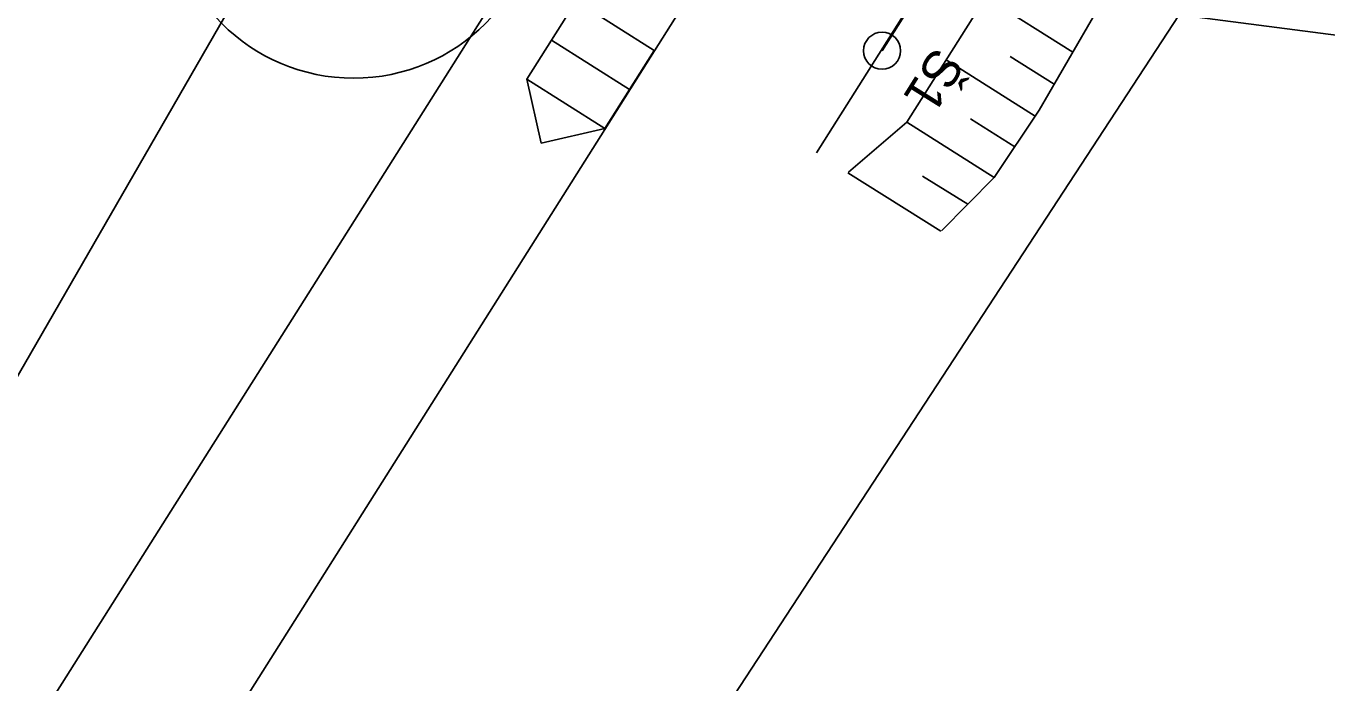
# Model space of a CAD drawing. Extents: x -746176 to -739709, y -1128407 to -1124482.
# Drawn here: x -743187.21 to -743169.62, y -1127113.64 to -1127104.75 of the extents above; entities that cross this region are included whole.
import ezdxf

# ---------------------------------------------------------------- set-up
doc = ezdxf.new("R2010")
doc.units = 0
for name, color, linetype in [('_Zabezpečovací zařízení', 7, 'Continuous'), ('_Zabezpečovací zařízení_trasa', 7, 'Continuous'), ('Hranice parcel', 7, 'Continuous'), ('OSA', 7, 'Continuous'), ('SMER_VYS_VYROVNANI', 7, 'Continuous'), ('SVAH', 7, 'Continuous'), ('TRATIVOD', 7, 'Continuous'), ('Vrstva 53', 7, 'Continuous'), ('ŽBP', 7, 'Continuous')]:
    doc.layers.add(name, color=color, linetype=linetype)

msp = doc.modelspace()

# ---------------------------------------------------------------- linework, layer by layer
at = {"layer": '_Zabezpečovací zařízení'}
for p, q in [((-743179.773, -1127104.416), (-743180.44, -1127105.473)), ((-743178.716, -1127105.083), (-743179.773, -1127104.416)), ((-743179.05, -1127105.611), (-743180.107, -1127104.945)), ((-743179.383, -1127106.14), (-743178.716, -1127105.083)), ((-743180.44, -1127105.473), (-743179.383, -1127106.14)), ((-743180.44, -1127105.473), (-743180.245, -1127106.335)), ((-743180.245, -1127106.335), (-743179.383, -1127106.14))]:
    msp.add_line(p, q, dxfattribs=at)
msp.add_lwpolyline([(-743179.773, -1127104.416), (-743180.107, -1127104.945), (-743179.05, -1127105.611), (-743178.716, -1127105.083), (-743179.773, -1127104.416)], dxfattribs=at)
at = {"layer": '_Zabezpečovací zařízení_trasa'}
msp.add_lwpolyline([(-743018.819, -1126847.736), (-743049.28, -1126895.951), (-743072.487, -1126932.751), (-743098.647, -1126974.146), (-743125.94, -1127017.384), (-743152.604, -1127059.608), (-743175.023, -1127095.116), (-743199.163, -1127133.346), (-743215.971, -1127159.941), (-743232.818, -1127186.515), (-743247.456, -1127209.811), (-743254.52, -1127221.639), (-743261.299, -1127233.691), (-743264.155, -1127239.195), (-743264.862, -1127241.108), (-743267.337, -1127245.816), (-743268.289, -1127247.159), (-743271.711, -1127253.75), (-743281.122, -1127274.196), (-743291.923, -1127301.42), (-743296.724, -1127315.222), (-743301.116, -1127329.128), (-743306.787, -1127349.506)], dxfattribs=at)
at = {"layer": 'Hranice parcel'}
for q in [(-743183.01, -1127122.02), (-743100.85, -1127113.88)]:
    msp.add_line((-743171.62, -1127104.6), q, dxfattribs=at)
msp.add_lwpolyline([(-743280.26, -1127263.68), (-743264.54, -1127233.06), (-743246.95, -1127204.21), (-743235.54, -1127186.77), (-743205.03, -1127140.21), (-743183.34, -1127102.57)], dxfattribs=at)
at = {"layer": 'OSA'}
msp.add_lwpolyline([(-743169.53, -1127090.542), (-743178.712, -1127105.086)], dxfattribs=at)
at = {"layer": 'SMER_VYS_VYROVNANI'}
msp.add_lwpolyline([(-743178.712, -1127105.086), (-743197.526, -1127134.888)], dxfattribs=at)
at = {"layer": 'SVAH'}
for p, q in [((-743173.059, -1127105.107), (-743174.235, -1127104.364)), ((-743173.565, -1127105.97), (-743174.769, -1127105.21)), ((-743173.309, -1127105.54), (-743173.906, -1127105.163)), ((-743173.842, -1127106.386), (-743174.439, -1127106.009)), ((-743174.12, -1127106.803), (-743175.303, -1127106.055)), ((-743174.842, -1127107.529), (-743176.097, -1127106.736)), ((-743174.477, -1127107.163), (-743175.091, -1127106.782))]:
    msp.add_line(p, q, dxfattribs=at)
for points in [[(-743173.338, -1127101.419), (-743176.524, -1127106.467)], [(-743172.435, -1127101.512), (-743175.303, -1127106.055), (-743176.091, -1127106.731)], [(-743172.596, -1127104.307), (-743173.512, -1127105.891), (-743174.119, -1127106.803), (-743174.835, -1127107.522)]]:
    msp.add_lwpolyline(points, dxfattribs=at)
at = {"layer": 'TRATIVOD'}
msp.add_lwpolyline([(-743175.637, -1127105.086), (-743168.399, -1127093.621), (-743157.384, -1127076.172), (-743151.775, -1127072.311)], dxfattribs=at)
msp.add_circle((-743175.637, -1127105.086), 0.25, dxfattribs=at)
at = {"layer": 'Vrstva 53'}
for points in [[(-743312.01, -1127362.15), (-743304.91, -1127333.26), (-743304.3, -1127331.19), (-743293.07, -1127296.72), (-743292.92, -1127296.34), (-743280.26, -1127263.68), (-743264.54, -1127233.06), (-743246.95, -1127204.21), (-743235.54, -1127186.77), (-743205.03, -1127140.21), (-743183.34, -1127102.57)], [(-743183.34, -1127102.57), (-743171.62, -1127104.6), (-743183.01, -1127122.02), (-743195.51, -1127141.13), (-743203.92, -1127154.43), (-743215.95, -1127172.74), (-743210.36, -1127174.02), (-743237.28, -1127205.49), (-743245.75, -1127220.06), (-743259.48, -1127245.93), (-743268.91, -1127265.85), (-743283.26, -1127298.02), (-743294.99, -1127330.28), (-743295.73, -1127333.53), (-743296.23, -1127335.74), (-743299.98, -1127352.31)]]:
    msp.add_lwpolyline(points, dxfattribs=at)
at = {"layer": 'ŽBP'}
msp.add_circle((-743182.78, -1127102.938), 2.52, dxfattribs=at)

# ---------------------------------------------------------------- texts
at = {"layer": 'TRATIVOD'}
msp.add_text('Š1', height=0.5, rotation=238, dxfattribs=at).set_placement((-743174.927, -1127105.012))

doc.saveas('drawing.dxf')
